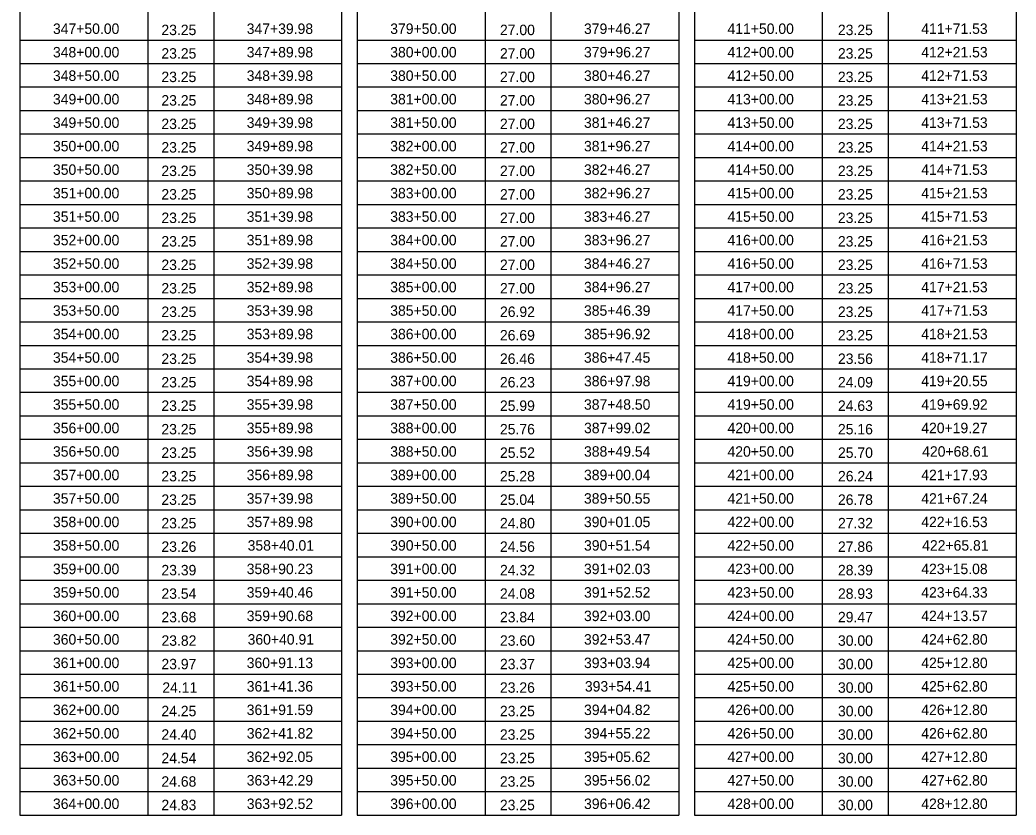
# Model space of a CAD drawing. Extents: x 1602163 to 1612907, y 1087635 to 1096265.
# Drawn here: x 1609604 to 1610177, y 1095298 to 1095755 of the extents above; entities that cross this region are included whole.
import ezdxf

# ---------------------------------------------------------------- set-up
doc = ezdxf.new("R2010")
doc.units = 0
doc.layers.add('RD_SHT_Misc1', color=7, linetype='Continuous')
doc.layers.add('RD_SHT_TX', color=7, linetype='Continuous')

msp = doc.modelspace()

# ---------------------------------------------------------------- linework, layer by layer
at = {"layer": 'RD_SHT_Misc1'}
for p, q in [((1609604.34, 1096189.84), (1609604.34, 1095297.84)), ((1609677.81, 1096189.84), (1609677.81, 1095297.84)), ((1609715.7, 1096189.84), (1609715.7, 1095297.84)), ((1609789.17, 1096189.84), (1609789.17, 1095297.84)), ((1609798.17, 1096189.84), (1609798.17, 1095297.84)), ((1609871.64, 1096189.84), (1609871.64, 1095297.84)), ((1609909.53, 1096189.84), (1609909.53, 1095297.84)), ((1609983, 1096189.84), (1609983, 1095297.84)), ((1609992, 1096189.84), (1609992, 1095297.84)), ((1610065.47, 1096189.84), (1610065.47, 1095297.84)), ((1610103.36, 1096189.84), (1610103.36, 1095297.84)), ((1610176.83, 1096189.84), (1610176.83, 1095297.84)), ((1609604.34, 1095743.34), (1609789.17, 1095743.34)), ((1609798.17, 1095743.34), (1609983, 1095743.34)), ((1609992, 1095743.34), (1610176.83, 1095743.34)), ((1609604.34, 1095729.84), (1609789.17, 1095729.84)), ((1609798.17, 1095729.84), (1609983, 1095729.84)), ((1609992, 1095729.84), (1610176.83, 1095729.84)), ((1609604.34, 1095716.34), (1609789.17, 1095716.34)), ((1609798.17, 1095716.34), (1609983, 1095716.34)), ((1609992, 1095716.34), (1610176.83, 1095716.34)), ((1609604.34, 1095702.84), (1609789.17, 1095702.84)), ((1609798.17, 1095702.84), (1609983, 1095702.84)), ((1609992, 1095702.84), (1610176.83, 1095702.84)), ((1609604.34, 1095689.34), (1609789.17, 1095689.34)), ((1609798.17, 1095689.34), (1609983, 1095689.34)), ((1609992, 1095689.34), (1610176.83, 1095689.34)), ((1609604.34, 1095675.84), (1609789.17, 1095675.84)), ((1609798.17, 1095675.84), (1609983, 1095675.84)), ((1609992, 1095675.84), (1610176.83, 1095675.84)), ((1609604.34, 1095662.34), (1609789.17, 1095662.34)), ((1609798.17, 1095662.34), (1609983, 1095662.34)), ((1609992, 1095662.34), (1610176.83, 1095662.34)), ((1609604.34, 1095648.84), (1609789.17, 1095648.84)), ((1609798.17, 1095648.84), (1609983, 1095648.84)), ((1609992, 1095648.84), (1610176.83, 1095648.84)), ((1609604.34, 1095635.34), (1609789.17, 1095635.34)), ((1609798.17, 1095635.34), (1609983, 1095635.34)), ((1609992, 1095635.34), (1610176.83, 1095635.34)), ((1609604.34, 1095621.84), (1609789.17, 1095621.84)), ((1609798.17, 1095621.84), (1609983, 1095621.84)), ((1609992, 1095621.84), (1610176.83, 1095621.84)), ((1609604.34, 1095608.34), (1609789.17, 1095608.34)), ((1609798.17, 1095608.34), (1609983, 1095608.34)), ((1609992, 1095608.34), (1610176.83, 1095608.34)), ((1609604.34, 1095594.84), (1609789.17, 1095594.84)), ((1609798.17, 1095594.84), (1609983, 1095594.84)), ((1609992, 1095594.84), (1610176.83, 1095594.84)), ((1609604.34, 1095581.34), (1609789.17, 1095581.34)), ((1609798.17, 1095581.34), (1609983, 1095581.34)), ((1609992, 1095581.34), (1610176.83, 1095581.34)), ((1609604.34, 1095567.84), (1609789.17, 1095567.84)), ((1609798.17, 1095567.84), (1609983, 1095567.84)), ((1609992, 1095567.84), (1610176.83, 1095567.84)), ((1609604.34, 1095554.34), (1609789.17, 1095554.34)), ((1609798.17, 1095554.34), (1609983, 1095554.34)), ((1609992, 1095554.34), (1610176.83, 1095554.34)), ((1609604.34, 1095540.84), (1609789.17, 1095540.84)), ((1609798.17, 1095540.84), (1609983, 1095540.84)), ((1609992, 1095540.84), (1610176.83, 1095540.84)), ((1609604.34, 1095527.34), (1609789.17, 1095527.34)), ((1609798.17, 1095527.34), (1609983, 1095527.34)), ((1609992, 1095527.34), (1610176.83, 1095527.34)), ((1609604.34, 1095513.84), (1609789.17, 1095513.84)), ((1609798.17, 1095513.84), (1609983, 1095513.84)), ((1609992, 1095513.84), (1610176.83, 1095513.84)), ((1609604.34, 1095500.34), (1609789.17, 1095500.34)), ((1609798.17, 1095500.34), (1609983, 1095500.34)), ((1609992, 1095500.34), (1610176.83, 1095500.34)), ((1609604.34, 1095486.84), (1609789.17, 1095486.84)), ((1609798.17, 1095486.84), (1609983, 1095486.84)), ((1609992, 1095486.84), (1610176.83, 1095486.84)), ((1609604.34, 1095473.34), (1609789.17, 1095473.34)), ((1609798.17, 1095473.34), (1609983, 1095473.34)), ((1609992, 1095473.34), (1610176.83, 1095473.34)), ((1609604.34, 1095459.84), (1609789.17, 1095459.84)), ((1609798.17, 1095459.84), (1609983, 1095459.84)), ((1609992, 1095459.84), (1610176.83, 1095459.84)), ((1609604.34, 1095446.34), (1609789.17, 1095446.34)), ((1609798.17, 1095446.34), (1609983, 1095446.34)), ((1609992, 1095446.34), (1610176.83, 1095446.34)), ((1609604.34, 1095432.84), (1609789.17, 1095432.84)), ((1609798.17, 1095432.84), (1609983, 1095432.84)), ((1609992, 1095432.84), (1610176.83, 1095432.84)), ((1609604.34, 1095419.34), (1609789.17, 1095419.34)), ((1609798.17, 1095419.34), (1609983, 1095419.34)), ((1609992, 1095419.34), (1610176.83, 1095419.34)), ((1609604.34, 1095405.84), (1609789.17, 1095405.84)), ((1609798.17, 1095405.84), (1609983, 1095405.84)), ((1609992, 1095405.84), (1610176.83, 1095405.84)), ((1609604.34, 1095392.34), (1609789.17, 1095392.34)), ((1609798.17, 1095392.34), (1609983, 1095392.34)), ((1609992, 1095392.34), (1610176.83, 1095392.34)), ((1609604.34, 1095378.84), (1609789.17, 1095378.84)), ((1609798.17, 1095378.84), (1609983, 1095378.84)), ((1609992, 1095378.84), (1610176.83, 1095378.84)), ((1609604.34, 1095365.34), (1609789.17, 1095365.34)), ((1609798.17, 1095365.34), (1609983, 1095365.34)), ((1609992, 1095365.34), (1610176.83, 1095365.34)), ((1609604.34, 1095351.84), (1609789.17, 1095351.84)), ((1609798.17, 1095351.84), (1609983, 1095351.84)), ((1609992, 1095351.84), (1610176.83, 1095351.84)), ((1609604.34, 1095338.34), (1609789.17, 1095338.34)), ((1609798.17, 1095338.34), (1609983, 1095338.34)), ((1609992, 1095338.34), (1610176.83, 1095338.34)), ((1609604.34, 1095324.84), (1609789.17, 1095324.84)), ((1609798.17, 1095324.84), (1609983, 1095324.84)), ((1609992, 1095324.84), (1610176.83, 1095324.84)), ((1609604.34, 1095311.34), (1609789.17, 1095311.34)), ((1609798.17, 1095311.34), (1609983, 1095311.34)), ((1609992, 1095311.34), (1610176.83, 1095311.34)), ((1609604.34, 1095297.84), (1609789.17, 1095297.84)), ((1609798.17, 1095297.84), (1609983, 1095297.84)), ((1609992, 1095297.84), (1610176.83, 1095297.84))]:
    msp.add_line(p, q, dxfattribs=at)

# ---------------------------------------------------------------- texts
at = {"layer": 'RD_SHT_TX'}
for s, p in [('347+50.00', (1609623.33, 1095746.84)), ('347+39.98', (1609734.68, 1095746.84)), ('379+50.00', (1609817.16, 1095746.84)), ('379+46.27', (1609928.51, 1095746.84)), ('411+50.00', (1610010.99, 1095746.84)), ('411+71.53', (1610122.34, 1095746.84)), ('23.25', (1609685.64, 1095746.15)), ('27.00', (1609880.22, 1095746.15)), ('23.25', (1610074.45, 1095746.15)), ('348+00.00', (1609623.33, 1095733.34)), ('23.25', (1609685.64, 1095732.65)), ('347+89.98', (1609734.68, 1095733.34)), ('380+00.00', (1609817.16, 1095733.34)), ('27.00', (1609880.22, 1095732.65)), ('379+96.27', (1609928.51, 1095733.34)), ('412+00.00', (1610010.99, 1095733.34)), ('23.25', (1610074.45, 1095732.65)), ('412+21.53', (1610122.34, 1095733.34)), ('348+50.00', (1609623.33, 1095719.84)), ('23.25', (1609685.64, 1095719.15)), ('348+39.98', (1609734.68, 1095719.84)), ('380+50.00', (1609817.16, 1095719.84)), ('27.00', (1609880.22, 1095719.15)), ('380+46.27', (1609928.51, 1095719.84)), ('412+50.00', (1610010.99, 1095719.84)), ('23.25', (1610074.45, 1095719.15)), ('412+71.53', (1610122.34, 1095719.84)), ('349+00.00', (1609623.33, 1095706.34)), ('23.25', (1609685.64, 1095705.65)), ('348+89.98', (1609734.68, 1095706.34)), ('381+00.00', (1609817.16, 1095706.34)), ('27.00', (1609880.22, 1095705.65)), ('380+96.27', (1609928.51, 1095706.34)), ('413+00.00', (1610010.99, 1095706.34)), ('23.25', (1610074.45, 1095705.65)), ('413+21.53', (1610122.34, 1095706.34)), ('349+50.00', (1609623.33, 1095692.84)), ('23.25', (1609685.64, 1095692.15)), ('349+39.98', (1609734.68, 1095692.84)), ('381+50.00', (1609817.16, 1095692.84)), ('27.00', (1609880.22, 1095692.15)), ('381+46.27', (1609928.51, 1095692.84)), ('413+50.00', (1610010.99, 1095692.84)), ('23.25', (1610074.45, 1095692.15)), ('413+71.53', (1610122.34, 1095692.84)), ('350+00.00', (1609623.33, 1095679.34)), ('23.25', (1609685.64, 1095678.65)), ('349+89.98', (1609734.68, 1095679.34)), ('382+00.00', (1609817.16, 1095679.34)), ('27.00', (1609880.22, 1095678.65)), ('381+96.27', (1609928.51, 1095679.34)), ('414+00.00', (1610010.99, 1095679.34)), ('23.25', (1610074.45, 1095678.65)), ('414+21.53', (1610122.34, 1095679.34)), ('350+50.00', (1609623.33, 1095665.84)), ('23.25', (1609685.64, 1095665.15)), ('350+39.98', (1609734.68, 1095665.84)), ('382+50.00', (1609817.16, 1095665.84)), ('27.00', (1609880.22, 1095665.15)), ('382+46.27', (1609928.51, 1095665.84)), ('414+50.00', (1610010.99, 1095665.84)), ('23.25', (1610074.45, 1095665.15)), ('414+71.53', (1610122.34, 1095665.84)), ('351+00.00', (1609623.33, 1095652.34)), ('23.25', (1609685.64, 1095651.65)), ('350+89.98', (1609734.68, 1095652.34)), ('383+00.00', (1609817.16, 1095652.34)), ('27.00', (1609880.22, 1095651.65)), ('382+96.27', (1609928.51, 1095652.34)), ('415+00.00', (1610010.99, 1095652.34)), ('23.25', (1610074.45, 1095651.65)), ('415+21.53', (1610122.34, 1095652.34)), ('351+50.00', (1609623.33, 1095638.84)), ('23.25', (1609685.64, 1095638.15)), ('351+39.98', (1609734.68, 1095638.84)), ('383+50.00', (1609817.16, 1095638.84)), ('27.00', (1609880.22, 1095638.15)), ('383+46.27', (1609928.51, 1095638.84)), ('415+50.00', (1610010.99, 1095638.84)), ('23.25', (1610074.45, 1095638.15)), ('415+71.53', (1610122.34, 1095638.84)), ('352+00.00', (1609623.33, 1095625.34)), ('23.25', (1609685.64, 1095624.65)), ('351+89.98', (1609734.68, 1095625.34)), ('384+00.00', (1609817.16, 1095625.34)), ('27.00', (1609880.22, 1095624.65)), ('383+96.27', (1609928.51, 1095625.34)), ('416+00.00', (1610010.99, 1095625.34)), ('23.25', (1610074.45, 1095624.65)), ('416+21.53', (1610122.34, 1095625.34)), ('352+50.00', (1609623.33, 1095611.84)), ('23.25', (1609685.64, 1095611.15)), ('352+39.98', (1609734.68, 1095611.84)), ('384+50.00', (1609817.16, 1095611.84)), ('27.00', (1609880.22, 1095611.15)), ('384+46.27', (1609928.51, 1095611.84)), ('416+50.00', (1610010.99, 1095611.84)), ('23.25', (1610074.45, 1095611.15)), ('416+71.53', (1610122.34, 1095611.84)), ('353+00.00', (1609623.33, 1095598.34)), ('352+89.98', (1609734.68, 1095598.34)), ('385+00.00', (1609817.16, 1095598.34)), ('384+96.27', (1609928.51, 1095598.34)), ('417+00.00', (1610010.99, 1095598.34)), ('417+21.53', (1610122.34, 1095598.34)), ('23.25', (1609685.64, 1095597.65)), ('27.00', (1609880.22, 1095597.65)), ('23.25', (1610074.45, 1095597.65)), ('353+50.00', (1609623.33, 1095584.84)), ('23.25', (1609685.64, 1095584.15)), ('353+39.98', (1609734.68, 1095584.84)), ('385+50.00', (1609817.16, 1095584.84)), ('26.92', (1609880.24, 1095584.15)), ('385+46.39', (1609928.51, 1095584.84)), ('417+50.00', (1610010.99, 1095584.84)), ('23.25', (1610074.45, 1095584.15)), ('417+71.53', (1610122.34, 1095584.84)), ('354+00.00', (1609623.33, 1095571.34)), ('23.25', (1609685.64, 1095570.65)), ('353+89.98', (1609734.68, 1095571.34)), ('386+00.00', (1609817.16, 1095571.34)), ('26.69', (1609880.21, 1095570.65)), ('385+96.92', (1609928.54, 1095571.34)), ('418+00.00', (1610010.99, 1095571.34)), ('23.25', (1610074.45, 1095570.65)), ('418+21.53', (1610122.34, 1095571.34)), ('354+50.00', (1609623.33, 1095557.84)), ('23.25', (1609685.64, 1095557.15)), ('354+39.98', (1609734.68, 1095557.84)), ('386+50.00', (1609817.16, 1095557.84)), ('26.46', (1609880.21, 1095557.15)), ('386+47.45', (1609928.49, 1095557.84)), ('418+50.00', (1610010.99, 1095557.84)), ('23.56', (1610074.47, 1095557.15)), ('418+71.17', (1610122.34, 1095557.84)), ('355+00.00', (1609623.33, 1095544.34)), ('23.25', (1609685.64, 1095543.65)), ('354+89.98', (1609734.68, 1095544.34)), ('387+00.00', (1609817.16, 1095544.34)), ('26.23', (1609880.21, 1095543.65)), ('386+97.98', (1609928.51, 1095544.34)), ('419+00.00', (1610010.99, 1095544.34)), ('24.09', (1610074.47, 1095543.65)), ('419+20.55', (1610122.32, 1095544.34)), ('355+50.00', (1609623.33, 1095530.84)), ('23.25', (1609685.64, 1095530.15)), ('355+39.98', (1609734.68, 1095530.84)), ('387+50.00', (1609817.16, 1095530.84)), ('25.99', (1609880.21, 1095530.15)), ('387+48.50', (1609928.52, 1095530.84)), ('419+50.00', (1610010.99, 1095530.84)), ('24.63', (1610074.47, 1095530.15)), ('419+69.92', (1610122.37, 1095530.84)), ('356+00.00', (1609623.33, 1095517.34)), ('23.25', (1609685.64, 1095516.65)), ('355+89.98', (1609734.68, 1095517.34)), ('388+00.00', (1609817.16, 1095517.34)), ('25.76', (1609880.21, 1095516.65)), ('387+99.02', (1609928.54, 1095517.34)), ('420+00.00', (1610010.99, 1095517.34)), ('25.16', (1610074.47, 1095516.65)), ('420+19.27', (1610122.34, 1095517.34)), ('356+50.00', (1609623.33, 1095503.84)), ('23.25', (1609685.64, 1095503.15)), ('356+39.98', (1609734.68, 1095503.84)), ('388+50.00', (1609817.16, 1095503.84)), ('25.52', (1609880.24, 1095503.15)), ('388+49.54', (1609928.52, 1095503.84)), ('420+50.00', (1610010.99, 1095503.84)), ('25.70', (1610074.48, 1095503.15)), ('420+68.61', (1610122.86, 1095503.84)), ('357+00.00', (1609623.33, 1095490.34)), ('23.25', (1609685.64, 1095489.65)), ('356+89.98', (1609734.68, 1095490.34)), ('389+00.00', (1609817.16, 1095490.34)), ('25.28', (1609880.21, 1095489.65)), ('389+00.04', (1609928.52, 1095490.34)), ('421+00.00', (1610010.99, 1095490.34)), ('26.24', (1610074.49, 1095489.65)), ('421+17.93', (1610122.34, 1095490.34)), ('357+50.00', (1609623.33, 1095476.84)), ('23.25', (1609685.64, 1095476.15)), ('357+39.98', (1609734.68, 1095476.84)), ('389+50.00', (1609817.16, 1095476.84)), ('25.04', (1609880.22, 1095476.15)), ('389+50.55', (1609928.49, 1095476.84)), ('421+50.00', (1610010.99, 1095476.84)), ('26.78', (1610074.47, 1095476.15)), ('421+67.24', (1610122.35, 1095476.84)), ('358+00.00', (1609623.33, 1095463.34)), ('23.25', (1609685.64, 1095462.65)), ('357+89.98', (1609734.68, 1095463.34)), ('390+00.00', (1609817.16, 1095463.34)), ('24.80', (1609880.22, 1095462.65)), ('390+01.05', (1609928.49, 1095463.34)), ('422+00.00', (1610010.99, 1095463.34)), ('27.32', (1610074.5, 1095462.65)), ('422+16.53', (1610122.34, 1095463.34)), ('358+50.00', (1609623.33, 1095449.84)), ('23.26', (1609685.66, 1095449.15)), ('358+40.01', (1609735.2, 1095449.84)), ('390+50.00', (1609817.16, 1095449.84)), ('24.56', (1609880.21, 1095449.15)), ('390+51.54', (1609928.52, 1095449.84)), ('422+50.00', (1610010.99, 1095449.84)), ('27.86', (1610074.47, 1095449.15)), ('422+65.81', (1610122.86, 1095449.84)), ('359+00.00', (1609623.33, 1095436.34)), ('23.39', (1609685.65, 1095435.65)), ('358+90.23', (1609734.68, 1095436.34)), ('391+00.00', (1609817.16, 1095436.34)), ('24.32', (1609880.24, 1095435.65)), ('391+02.03', (1609928.51, 1095436.34)), ('423+00.00', (1610010.99, 1095436.34)), ('28.39', (1610074.47, 1095435.65)), ('423+15.08', (1610122.34, 1095436.34)), ('359+50.00', (1609623.33, 1095422.84)), ('23.54', (1609685.67, 1095422.15)), ('359+40.46', (1609734.68, 1095422.84)), ('391+50.00', (1609817.16, 1095422.84)), ('24.08', (1609880.21, 1095422.15)), ('391+52.52', (1609928.54, 1095422.84)), ('423+50.00', (1610010.99, 1095422.84)), ('28.93', (1610074.47, 1095422.15)), ('423+64.33', (1610122.34, 1095422.84)), ('360+00.00', (1609623.33, 1095409.34)), ('359+90.68', (1609734.68, 1095409.34)), ('392+00.00', (1609817.16, 1095409.34)), ('392+03.00', (1609928.52, 1095409.34)), ('424+00.00', (1610010.99, 1095409.34)), ('424+13.57', (1610122.34, 1095409.34)), ('23.68', (1609685.65, 1095408.65)), ('23.84', (1609880.22, 1095408.65)), ('29.47', (1610074.47, 1095408.65)), ('360+50.00', (1609623.33, 1095395.84)), ('23.82', (1609685.69, 1095395.15)), ('360+40.91', (1609735.2, 1095395.84)), ('392+50.00', (1609817.16, 1095395.84)), ('23.60', (1609880.22, 1095395.15)), ('392+53.47', (1609928.51, 1095395.84)), ('424+50.00', (1610010.99, 1095395.84)), ('30.00', (1610074.48, 1095395.15)), ('424+62.80', (1610122.35, 1095395.84)), ('361+00.00', (1609623.33, 1095382.34)), ('23.97', (1609685.66, 1095381.65)), ('360+91.13', (1609734.68, 1095382.34)), ('393+00.00', (1609817.16, 1095382.34)), ('23.37', (1609880.21, 1095381.65)), ('393+03.94', (1609928.52, 1095382.34)), ('425+00.00', (1610010.99, 1095382.34)), ('30.00', (1610074.48, 1095381.65)), ('425+12.80', (1610122.35, 1095382.34)), ('361+50.00', (1609623.33, 1095368.84)), ('24.11', (1609686.18, 1095368.15)), ('361+41.36', (1609734.68, 1095368.84)), ('393+50.00', (1609817.16, 1095368.84)), ('23.26', (1609880.21, 1095368.15)), ('393+54.41', (1609929.03, 1095368.84)), ('425+50.00', (1610010.99, 1095368.84)), ('30.00', (1610074.48, 1095368.15)), ('425+62.80', (1610122.35, 1095368.84)), ('362+00.00', (1609623.33, 1095355.34)), ('24.25', (1609685.64, 1095354.65)), ('361+91.59', (1609734.68, 1095355.34)), ('394+00.00', (1609817.16, 1095355.34)), ('23.25', (1609880.19, 1095354.65)), ('394+04.82', (1609928.54, 1095355.34)), ('426+00.00', (1610010.99, 1095355.34)), ('30.00', (1610074.48, 1095354.65)), ('426+12.80', (1610122.35, 1095355.34)), ('362+50.00', (1609623.33, 1095341.84)), ('24.40', (1609685.67, 1095341.15)), ('362+41.82', (1609734.71, 1095341.84)), ('394+50.00', (1609817.16, 1095341.84)), ('23.25', (1609880.19, 1095341.15)), ('394+55.22', (1609928.54, 1095341.84)), ('426+50.00', (1610010.99, 1095341.84)), ('30.00', (1610074.48, 1095341.15)), ('426+62.80', (1610122.35, 1095341.84)), ('363+00.00', (1609623.33, 1095328.34)), ('24.54', (1609685.67, 1095327.65)), ('362+92.05', (1609734.66, 1095328.34)), ('395+00.00', (1609817.16, 1095328.34)), ('23.25', (1609880.19, 1095327.65)), ('395+05.62', (1609928.54, 1095328.34)), ('427+00.00', (1610010.99, 1095328.34)), ('30.00', (1610074.48, 1095327.65)), ('427+12.80', (1610122.35, 1095328.34)), ('363+50.00', (1609623.33, 1095314.84)), ('24.68', (1609685.65, 1095314.15)), ('363+42.29', (1609734.68, 1095314.84)), ('395+50.00', (1609817.16, 1095314.84)), ('23.25', (1609880.19, 1095314.15)), ('395+56.02', (1609928.54, 1095314.84)), ('427+50.00', (1610010.99, 1095314.84)), ('30.00', (1610074.48, 1095314.15)), ('427+62.80', (1610122.35, 1095314.84)), ('364+00.00', (1609623.33, 1095301.34)), ('24.83', (1609685.66, 1095300.65)), ('363+92.52', (1609734.71, 1095301.34)), ('396+00.00', (1609817.16, 1095301.34)), ('23.25', (1609880.19, 1095300.65)), ('396+06.42', (1609928.54, 1095301.34)), ('428+00.00', (1610010.99, 1095301.34)), ('30.00', (1610074.48, 1095300.65)), ('428+12.80', (1610122.35, 1095301.34))]:
    msp.add_text(s, height=6, dxfattribs=at).set_placement(p)

doc.saveas('drawing.dxf')
